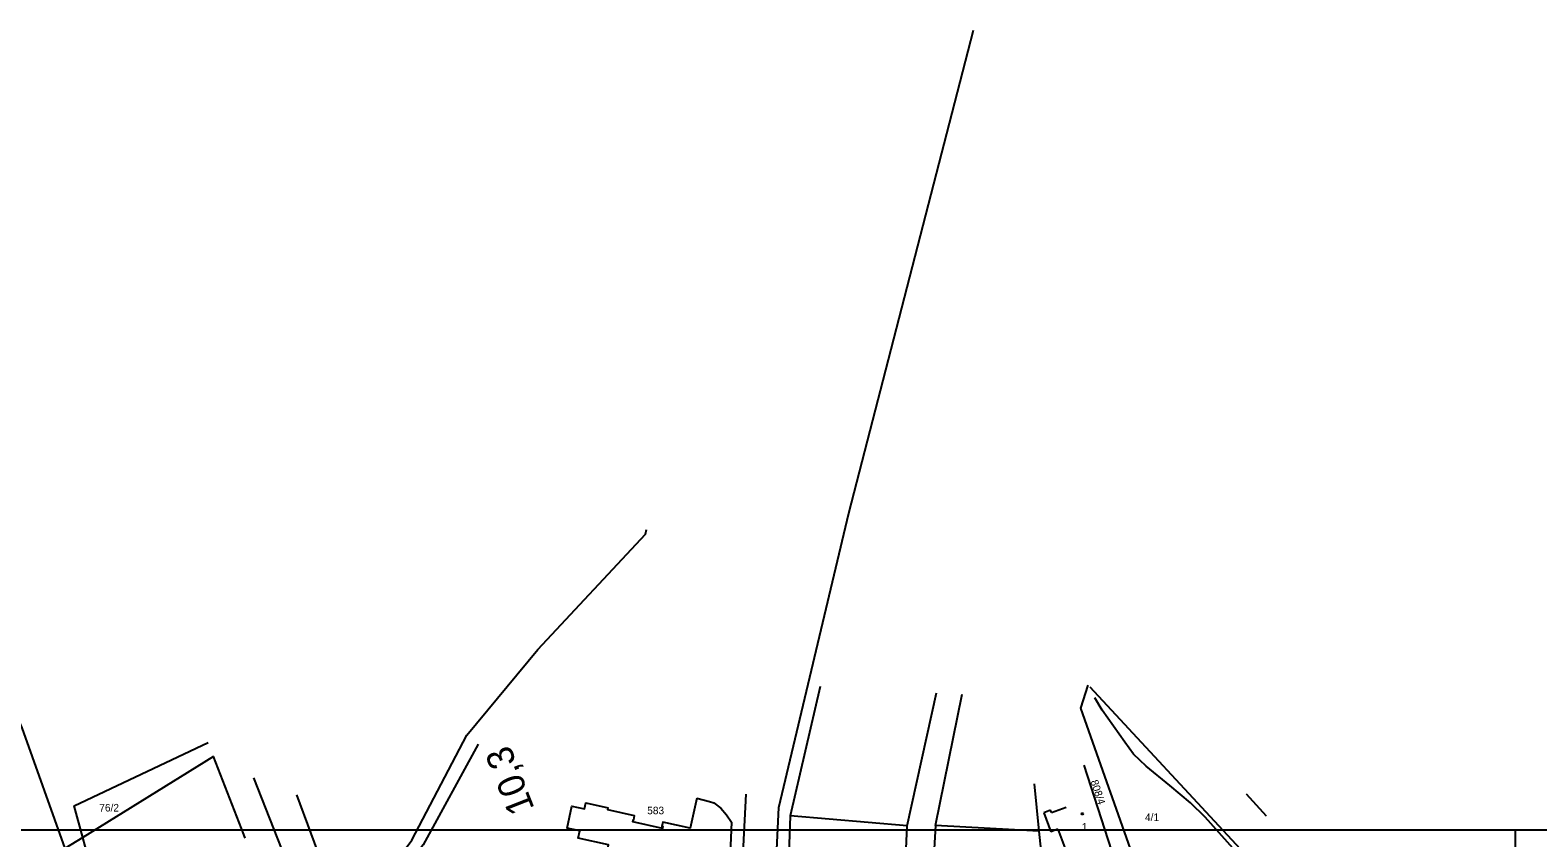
# Model space of a CAD drawing. Extents: x -553916 to -552953, y -1067469 to -1066637.
# Drawn here: x -553633.4 to -553294.9, y -1066818.1 to -1066636.6 of the extents above; entities that cross this region are included whole.
import ezdxf

# ---------------------------------------------------------------- set-up
doc = ezdxf.new("R2010")
doc.units = 0
for name, color, linetype in [('Hranice parcel', 7, 'Continuous'), ('Kolej', 7, 'Continuous'), ('Návěst místo trati', 7, 'Continuous'), ('Parcelní čísla', 7, 'Continuous'), ('Vnitřní kresba', 7, 'Continuous'), ('Vrstva 1', 7, 'Continuous'), ('Značky budov', 7, 'Continuous')]:
    doc.layers.add(name, color=color, linetype=linetype)

msp = doc.modelspace()

# ---------------------------------------------------------------- linework, layer by layer
at = {"layer": 'Hranice parcel'}
for p, q in [((-553456.02, -1066784.1), (-553462.79, -1066813.1)), ((-553436.47, -1066815.36), (-553429.88, -1066785.49)), ((-553430.14, -1066815.28), (-553424.14, -1066785.8)), ((-553395.45, -1066784.17), (-553361.7, -1066820.54)), ((-553592.22, -1066799.8), (-553621.6, -1066817.99)), ((-553407.99, -1066805.97), (-553406.9, -1066816.6)), ((-553407.99, -1066805.97), (-553406.9, -1066816.6)), ((-553473.84, -1066830.72), (-553472.63, -1066808.29)), ((-553360.35, -1066808.19), (-553355.86, -1066813.11)), ((-553462.79, -1066813.1), (-553463.9, -1066843.58)), ((-553436.47, -1066815.36), (-553462.79, -1066813.1)), ((-553362.67, -1066821.17), (-553369.61, -1066813.45)), ((-553437.72, -1066844.45), (-553436.47, -1066815.36)), ((-553430.14, -1066815.28), (-553430.74, -1066826)), ((-553406.9, -1066816.6), (-553430.14, -1066815.28)), ((-553406.9, -1066816.6), (-553405.9, -1066826.43)), ((-553406.9, -1066816.6), (-553405.9, -1066826.43)), ((-553621.6, -1066817.99), (-553625.66, -1066820.5)), ((-553617.57, -1066832.95), (-553621.6, -1066817.99))]:
    msp.add_line(p, q, dxfattribs=at)
for points in [[(-553477.08, -1066903.52), (-553471.25, -1066891.92), (-553468.41, -1066870.82), (-553466.8, -1066842.82), (-553465.31, -1066811.26), (-553449.58, -1066745.18), (-553421.6, -1066636.65)], [(-553562.46, -1066838.44), (-553547.69, -1066818.62), (-553535.38, -1066795.04), (-553519.42, -1066775.8), (-553495.28, -1066749.85), (-553495.01, -1066748.81)], [(-553643.88, -1066774.03), (-553635.29, -1066793.34), (-553625.66, -1066820.5)], [(-553384.58, -1066825.61), (-553397.51, -1066788.92), (-553395.83, -1066783.77)], [(-553369.61, -1066813.45), (-553372.88, -1066810.21), (-553377.49, -1066806.31), (-553382.84, -1066801.95), (-553385.65, -1066799.3), (-553387.62, -1066796.6), (-553392.69, -1066789.37), (-553394.35, -1066786.66)], [(-553621.6, -1066817.99), (-553623.51, -1066810.9), (-553593.45, -1066796.65)], [(-553532.8, -1066797.02), (-553545.17, -1066819.67), (-553553.48, -1066830.52), (-553560.01, -1066844.54)], [(-553389.03, -1066825.78), (-553390.55, -1066821.01), (-553396.74, -1066801.73)], [(-553483.73, -1066809.15), (-553485.25, -1066815.92), (-553491.35, -1066814.56), (-553491.57, -1066815.51), (-553491.38, -1066815.55), (-553491.47, -1066815.96), (-553498.12, -1066814.47), (-553498.04, -1066814), (-553497.9, -1066814.03), (-553497.69, -1066813.13), (-553503.74, -1066811.77), (-553503.64, -1066811.31)], [(-553483.73, -1066809.15), (-553480.88, -1066809.9), (-553479.9, -1066810.22), (-553478.34, -1066811.42), (-553477.07, -1066812.9), (-553475.95, -1066814.54), (-553476.7, -1066832.08)], [(-553500.33, -1066835.91), (-553506.92, -1066834.42), (-553503.58, -1066819.65), (-553510.37, -1066818.12), (-553510, -1066816.53), (-553512.88, -1066815.92), (-553511.82, -1066810.98), (-553508.93, -1066811.58), (-553508.63, -1066810.19), (-553503.64, -1066811.31)]]:
    msp.add_lwpolyline(points, dxfattribs=at)
at = {"layer": 'Kolej'}
msp.add_lwpolyline([(-553503.32, -1067065.81), (-553502.68, -1067054.03), (-553502.76, -1067041.5), (-553503.63, -1067029.06), (-553504.76, -1067019.97), (-553506.18, -1067011.39), (-553508.33, -1067001.39), (-553510.95, -1066991.62), (-553512.92, -1066985.29), (-553515.65, -1066977.35), (-553517.42, -1066972.53), (-553519.16, -1066967.95), (-553522.89, -1066958.38), (-553529.1, -1066942.55), (-553538.69, -1066918.11), (-553542.91, -1066907.33), (-553546.69, -1066897.68), (-553555.03, -1066876.44), (-553564.64, -1066851.89), (-553574.24, -1066827.43), (-553583.19, -1066804.62)], dxfattribs=at)
at = {"layer": 'Vnitřní kresba'}
for p, q in [((-553404.33, -1066811.86), (-553405.84, -1066812.43)), ((-553405.84, -1066812.43), (-553404.21, -1066816.73)), ((-553404.12, -1066812.42), (-553404.33, -1066811.86)), ((-553404.12, -1066812.42), (-553400.79, -1066811.17)), ((-553402.7, -1066816.16), (-553404.21, -1066816.73)), ((-553402.7, -1066816.16), (-553399.76, -1066823.95))]:
    msp.add_line(p, q, dxfattribs=at)
at = {"layer": 'Vrstva 1'}
for p, q in [((-553573.62, -1066808.38), (-553562.46, -1066838.44)), ((-553794.11, -1066816.27), (-552953.11, -1066816.27))]:
    msp.add_line(p, q, dxfattribs=at)
for points in [[(-553585.12, -1066818.17), (-553585.42, -1066817.3), (-553592.22, -1066799.8)], [(-553300, -1066816.27), (-553300, -1067100), (-553800, -1067100), (-553800, -1066816.27)]]:
    msp.add_lwpolyline(points, dxfattribs=at)
at = {"layer": 'Značky budov'}
msp.add_circle((-553397.19, -1066812.68), 0.175, dxfattribs=at)

# ---------------------------------------------------------------- texts
at = {"layer": 'Návěst místo trati'}
msp.add_text('10,3', height=6, rotation=111.396, dxfattribs=at).set_placement((-553520.11, -1066811.5))
at = {"layer": 'Parcelní čísla'}
msp.add_text('808/4', height=1.7, rotation=288, dxfattribs=at).set_placement((-553395.33, -1066805.38))
for s, p in [('76/2', (-553617.9, -1066812.16)), ('583', (-553494.87, -1066812.78)), ('4/1', (-553383.1, -1066814.3)), ('1', (-553397.3, -1066816.47))]:
    msp.add_text(s, height=1.7, dxfattribs=at).set_placement(p)

doc.saveas('drawing.dxf')
